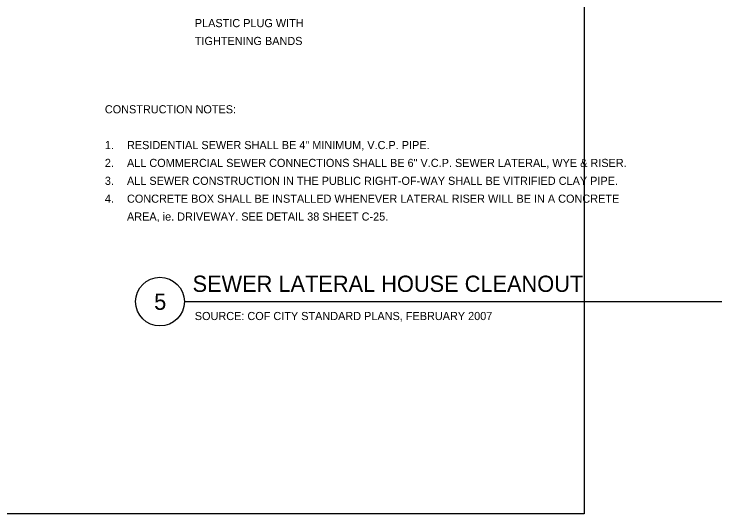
# Model space of a CAD drawing. Extents: x -1680 to 1155, y -802 to 799.
# Drawn here: x 633 to 1155, y -802 to -433 of the extents above; entities that cross this region are included whole.
import ezdxf

# ---------------------------------------------------------------- set-up
doc = ezdxf.new("R2010")
doc.units = 0
for name, color, linetype in [('G-TTLB-VIEW', 7, 'Continuous'), ('Misc CnstDet(22)', 7, 'Continuous'), ('Nongeo Data(60)', 7, 'Continuous')]:
    doc.layers.add(name, color=color, linetype=linetype)

msp = doc.modelspace()

# ---------------------------------------------------------------- linework, layer by layer
at = {"layer": 'G-TTLB-VIEW'}
msp.add_lwpolyline([(-548.79, 598.03), (1053.55, 598.03), (1053.55, -801.99), (-548.79, -801.99)], close=True, dxfattribs=at)
at = {"layer": 'Nongeo Data(60)'}
msp.add_line((758.67, -645.39), (1154.94, -645.39), dxfattribs=at)
msp.add_circle((740.67, -645.39), 18, dxfattribs=at)

# ---------------------------------------------------------------- texts
at = {"layer": 'Misc CnstDet(22)'}
for s, height, p in [('PLASTIC PLUG WITH', 6, (766.38, -442.92)), ('TIGHTENING BANDS', 6, (766.38, -456.11)), ('CONSTRUCTION NOTES:', 6, (700.04, -506.52)), ('1.', 6, (700.04, -532.9)), ('RESIDENTIAL SEWER SHALL BE 4" MINIMUM, V.C.P. PIPE.', 6, (716.36, -532.9)), ('2.', 6, (700.04, -546.09)), ('ALL COMMERCIAL SEWER CONNECTIONS SHALL BE 6" V.C.P. SEWER LATERAL, WYE & RISER.', 6, (716.36, -546.09)), ('3.', 6, (700.04, -559.28)), ('ALL SEWER CONSTRUCTION IN THE PUBLIC RIGHT-OF-WAY SHALL BE VITRIFIED CLAY PIPE.', 6, (716.36, -559.28)), ('4.', 6, (700.04, -572.46)), ('CONCRETE BOX SHALL BE INSTALLED WHENEVER LATERAL RISER WILL BE IN A CONCRETE', 6, (716.36, -572.46)), ('AREA, ie. DRIVEWAY. SEE DETAIL 38 SHEET C-25.', 6, (716.36, -585.65)), ('SEWER LATERAL HOUSE CLEANOUT', 12, (764.71, -638.23)), ('5', 12, (736.4, -651.45)), ('SOURCE: COF CITY STANDARD PLANS, FEBRUARY 2007', 6, (766.36, -659.02))]:
    msp.add_text(s, height=height, dxfattribs=at).set_placement(p)

doc.saveas('drawing.dxf')
